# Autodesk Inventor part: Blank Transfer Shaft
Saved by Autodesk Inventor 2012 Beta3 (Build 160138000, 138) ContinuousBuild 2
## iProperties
Created: 2011-01
Part Number: Blank Transfer Shaft
Material: Steel
Document SubType Name: Modeling
Designer: Beta-8540w
Density: 1 g/cm^3
CustomPartVersion: 1
Author: Beta-8540w
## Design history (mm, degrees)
sketch "Main Sketch"
  geometry: L1 (0, 0)-(51, 0) reference; L2 (0, 0)-(0, 5); L3 (0, 5)-(10, 5); L4 (10, 5)-(10, 6); L5 (10, 6)-(13, 6); L6 (13, 6)-(13, 12.5); L7 (25, 12.5)-(25, 6); L8 (13, 12.5)-(25, 12.5); L9 (41, 6)-(41, 5); L10 (25, 6)-(41, 6); L11 (51, 5)-(51, 0); L12 (41, 5)-(51, 5)
  constraints: 24 end point, 7 horizontal, 6 vertical
  dimensions: "d3" = 10 diameter of L3 L1 (derived); "d4" = 12 diameter of L5 L1 (derived); "d5" = 25 diameter of L8 L1 (derived); "d6" = 12 diameter of L10 L1 (derived); "d7" = 10 diameter of L12 L1 (derived)
revolve "Revolution1" sketch "Main Sketch" stored, may be unused: angle "d8" = 0 deg
chamfer "Chamfer1" distance "d9" = 0.3; stored, may be unused: second distance "d10" = 0.125, angle "d11" = 45 deg
chamfer "Chamfer2" distance "d12" = 0.3; stored, may be unused: second distance "d13" = 0.125, angle "d14" = 45 deg
body "Solid1"
other parameters: "d0" = 0, "d1" = 0, "d2" = 0
